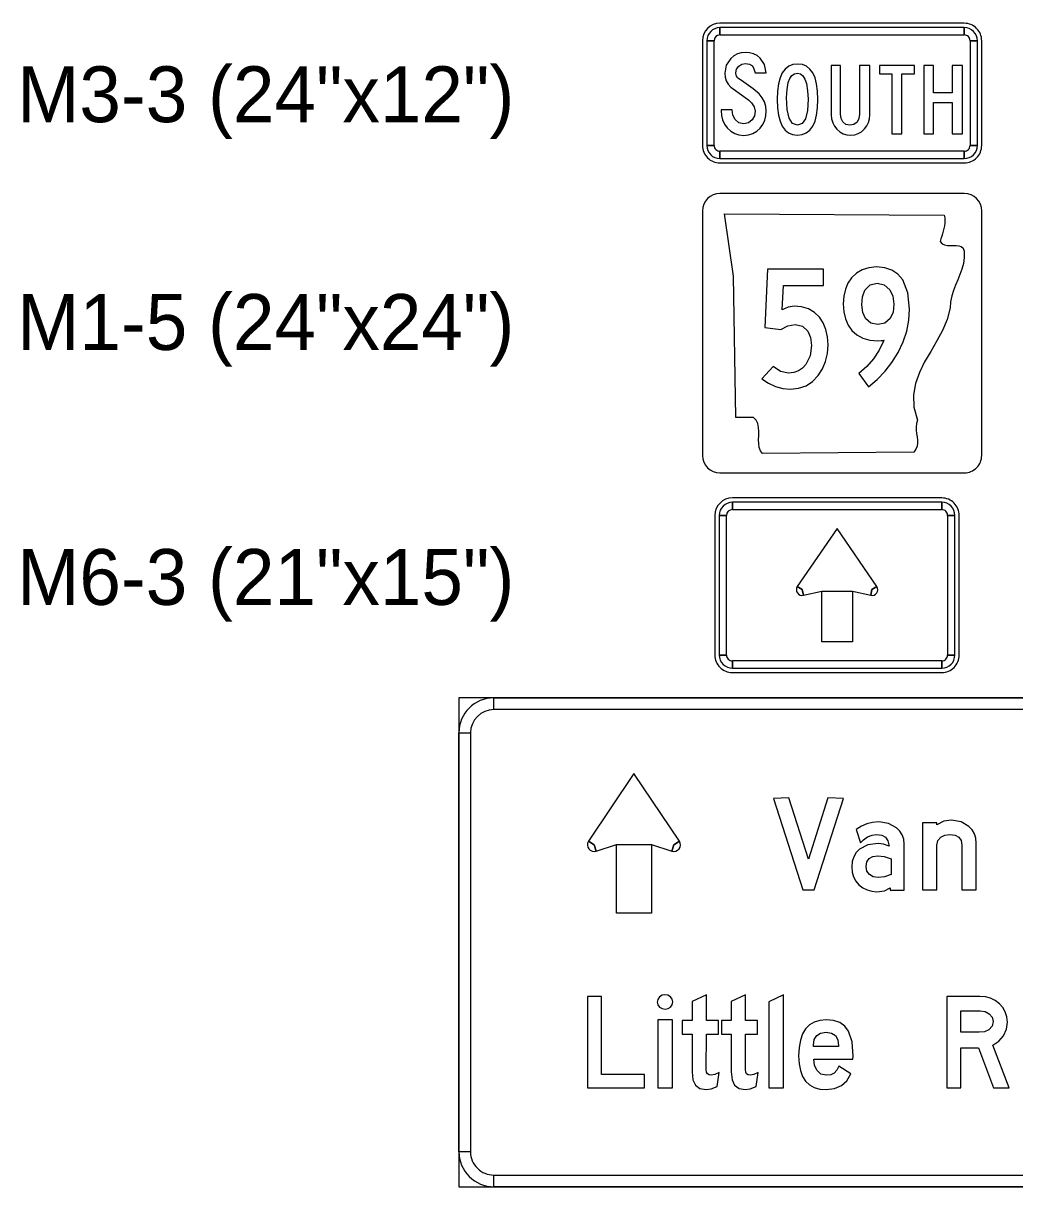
# Model space of a CAD drawing. Extents: x 620864 to 620948.6, y 415499.7 to 415559.1.
# Drawn here: x 620881.4 to 620888.5, y 415507.18 to 415515.51 of the extents above; entities that cross this region are included whole.
import ezdxf

# ---------------------------------------------------------------- set-up
doc = ezdxf.new("R2010")
doc.units = 0
doc.layers.add('G-Border-Paper', color=7, linetype='Continuous')
doc.layers.add('SIGNS', color=7, linetype='Continuous')

msp = doc.modelspace()

# ---------------------------------------------------------------- linework, layer by layer
at = {"layer": 'G-Border-Paper'}
for points in [[(620887.9953, 415514.1388), (620887.9999, 415514.1198), (620888.0016, 415514.1003), (620888.0009, 415514.0812), (620887.9986, 415514.0621), (620887.9946, 415514.043), (620887.9899, 415514.0243), (620887.9842, 415514.0052), (620887.9785, 415513.9869), (620887.9732, 415513.9685), (620887.9682, 415513.9501), (620887.9822, 415513.934), (620887.9996, 415513.9248), (620888.0193, 415513.9208), (620888.0407, 415513.9204), (620888.0621, 415513.9211), (620888.0828, 415513.9215), (620888.1018, 415513.9193), (620888.1185, 415513.9131), (620888.1316, 415513.9009), (620888.1396, 415513.8808), (620888.1403, 415513.8352), (620888.1346, 415513.7926), (620888.1239, 415513.7523), (620888.1095, 415513.7137), (620888.0938, 415513.6755), (620888.0777, 415513.6377), (620888.0627, 415513.5992), (620888.0507, 415513.5595), (620888.0424, 415513.518), (620888.0404, 415513.474), (620888.0183, 415513.3918), (620887.9845, 415513.3136), (620887.9438, 415513.2379), (620887.8996, 415513.163), (620887.8565, 415513.0885), (620887.8188, 415513.0125), (620887.7907, 415512.934), (620887.7763, 415512.8514), (620887.7797, 415512.764), (620887.8054, 415512.6704), (620887.7977, 415512.6472), (620887.7951, 415512.6234), (620887.7957, 415512.5995), (620887.7987, 415512.5753), (620887.8021, 415512.5514), (620887.8048, 415512.5279), (620887.8054, 415512.5048), (620887.8021, 415512.4831), (620887.7937, 415512.4619), (620887.7783, 415512.442), (620886.6946, 415512.4321), (620886.6799, 415512.4519), (620886.6716, 415512.4758), (620886.6679, 415512.5022), (620886.6676, 415512.5305), (620886.6682, 415512.5602), (620886.6686, 415512.5896), (620886.6666, 415512.6186), (620886.6609, 415512.6454), (620886.6499, 415512.6696), (620886.6315, 415512.6902), (620886.5052, 415512.6902), (620886.4871, 415513.702), (620886.4236, 415514.1487), (620887.9953, 415514.1388), (620887.9953, 415514.1388)], [(620886.6902, 415512.9672), (620886.7379, 415512.9342), (620886.7878, 415512.9109), (620886.84, 415512.8971), (620886.8947, 415512.8925), (620886.954, 415512.8985), (620887.0071, 415512.9166), (620887.0541, 415512.9471), (620887.095, 415512.9902), (620887.1257, 415513.0376), (620887.1476, 415513.0902), (620887.1608, 415513.1477), (620887.1654, 415513.2107), (620887.1616, 415513.2681), (620887.1499, 415513.3203), (620887.1307, 415513.3664), (620887.1035, 415513.407), (620887.067, 415513.4415), (620887.0246, 415513.4665), (620886.9756, 415513.4814), (620886.921, 415513.4866), (620886.8797, 415513.4799), (620886.8361, 415513.4598), (620886.8454, 415513.6352), (620887.1324, 415513.6352), (620887.1324, 415513.7507), (620886.7317, 415513.7507), (620886.7112, 415513.3348), (620886.8276, 415513.3198), (620886.8766, 415513.3458), (620886.9295, 415513.3546), (620886.9816, 415513.3427), (620887.0195, 415513.3079), (620887.0391, 415513.2619), (620887.0458, 415513.2049), (620887.0357, 415513.1302), (620887.0058, 415513.0691), (620886.9814, 415513.042), (620886.9526, 415513.0232), (620886.9194, 415513.0115), (620886.882, 415513.008), (620886.8247, 415513.0196), (620886.7709, 415513.0549)]]:
    msp.add_lwpolyline(points, close=True, dxfattribs=at)
for points in [[(620887.3857, 415513.0041), (620887.4546, 415512.909), (620887.517, 415512.9618), (620887.573, 415513.0203), (620887.6225, 415513.0842), (620887.6658, 415513.1539), (620887.7019, 415513.2303), (620887.7282, 415513.3074), (620887.7436, 415513.3853), (620887.7491, 415513.464), (620887.7365, 415513.5829), (620887.6991, 415513.6743), (620887.6642, 415513.7149), (620887.6215, 415513.744), (620887.5704, 415513.7613), (620887.5116, 415513.7673), (620887.4572, 415513.7623), (620887.4094, 415513.7479), (620887.3679, 415513.7237), (620887.3331, 415513.6898), (620887.3071, 415513.6512), (620887.2885, 415513.6073), (620887.2774, 415513.558), (620887.2738, 415513.5037), (620887.2774, 415513.4463), (620887.289, 415513.3955), (620887.3078, 415513.3512), (620887.3349, 415513.3133), (620887.3708, 415513.2803), (620887.4136, 415513.2568), (620887.4634, 415513.2429), (620887.5201, 415513.2383), (620887.5441, 415513.2398), (620887.5675, 415513.2416), (620887.565, 415513.2416), (620887.5315, 415513.1725), (620887.4904, 415513.1101), (620887.4417, 415513.0539), (620887.3857, 415513.0041)], [(620887.6369, 415513.5005), (620887.63, 415513.4438), (620887.6095, 415513.3992), (620887.5717, 415513.3657), (620887.5201, 415513.3546), (620887.4701, 415513.3651), (620887.4332, 415513.3974), (620887.4126, 415513.4412), (620887.4059, 415513.4961), (620887.4115, 415513.5542), (620887.429, 415513.6011), (620887.4652, 415513.639), (620887.516, 415513.6517), (620887.5675, 415513.6399), (620887.607, 415513.6045), (620887.6294, 415513.5573), (620887.6369, 415513.5005)]]:
    msp.add_lwpolyline(points, dxfattribs=at)
at = {"layer": 'SIGNS'}
for p, q in [((620888.1403, 415515.5122), (620886.3903, 415515.5122)), ((620886.3903, 415515.4289), (620886.3903, 415515.481)), ((620888.1403, 415515.481), (620888.1403, 415515.4289)), ((620886.2653, 415515.3872), (620886.2653, 415514.6372)), ((620886.2966, 415515.3872), (620886.3487, 415515.3872)), ((620888.182, 415515.3872), (620888.2341, 415515.3872)), ((620888.2653, 415514.6372), (620888.2653, 415515.3872)), ((620886.3487, 415514.6372), (620886.2966, 415514.6372)), ((620888.2341, 415514.6372), (620888.182, 415514.6372)), ((620886.3903, 415514.5435), (620886.3903, 415514.5956)), ((620888.1403, 415514.5956), (620888.1403, 415514.5435)), ((620886.3903, 415514.5122), (620888.1403, 415514.5122)), ((620888.1403, 415514.2932), (620886.3903, 415514.2932)), ((620886.2653, 415514.1682), (620886.2653, 415512.4182)), ((620888.2653, 415512.4182), (620888.2653, 415514.1682)), ((620886.2653, 415512.4182), (620886.2653, 415512.4182)), ((620886.3903, 415512.2932), (620888.1403, 415512.2932)), ((620887.9793, 415512.1134), (620886.4793, 415512.1134)), ((620886.4793, 415512.0301), (620886.4793, 415512.0821)), ((620887.9793, 415512.0821), (620887.9793, 415512.0301)), ((620886.3543, 415511.9884), (620886.3543, 415510.9884)), ((620886.3855, 415511.9884), (620886.4376, 415511.9884)), ((620888.0209, 415511.9884), (620888.073, 415511.9884)), ((620888.1043, 415510.9884), (620888.1043, 415511.9884)), ((620886.9793, 415511.4571), (620886.944, 415511.4794)), ((620886.9886, 415511.4165), (620886.9793, 415511.4571)), ((620887.4793, 415511.4571), (620887.4699, 415511.4165)), ((620887.5145, 415511.4794), (620887.4793, 415511.4571)), ((620886.4376, 415510.9884), (620886.3855, 415510.9884)), ((620886.4793, 415510.8946), (620886.4793, 415510.9467)), ((620887.9793, 415510.9467), (620887.9793, 415510.8946)), ((620888.073, 415510.9884), (620888.0209, 415510.9884)), ((620886.4793, 415510.8634), (620887.9793, 415510.8634)), ((620892.5209, 415510.6817), (620884.5209, 415510.6817)), ((620884.5209, 415510.6817), (620884.5209, 415507.1817)), ((620884.7709, 415510.5984), (620884.7709, 415510.6817)), ((620884.5209, 415510.4317), (620884.6042, 415510.4317)), ((620885.489, 415509.6309), (620885.4481, 415509.6562)), ((620885.5036, 415509.585), (620885.489, 415509.6309)), ((620886.0594, 415509.6309), (620886.0448, 415509.585)), ((620886.1003, 415509.6562), (620886.0594, 415509.6309)), ((620884.6042, 415507.4317), (620884.5209, 415507.4317)), ((620884.7709, 415507.1817), (620884.7709, 415507.265)), ((620884.5209, 415507.1817), (620892.5209, 415507.1817)), ((620884.5209, 415507.1817), (620884.5209, 415507.1817)), ((620884.5209, 415507.1817), (620884.5209, 415507.1817))]:
    msp.add_line(p, q, dxfattribs=at)
for points in [[(620888.1403, 415515.481), (620886.3903, 415515.481), (620886.3903, 415515.4289), (620888.1403, 415515.4289), (620888.1403, 415515.481), (620888.1403, 415515.481)], [(620886.2966, 415515.3872), (620886.2966, 415514.6372), (620886.3487, 415514.6372), (620886.3487, 415515.3872), (620886.2966, 415515.3872), (620886.2966, 415515.3872)], [(620888.2341, 415514.6372), (620888.2341, 415515.3872), (620888.182, 415515.3872), (620888.182, 415514.6372), (620888.2341, 415514.6372), (620888.2341, 415514.6372)], [(620886.399, 415514.8925), (620886.399, 415514.8872), (620886.4014, 415514.8524), (620886.4097, 415514.8201), (620886.4237, 415514.7905), (620886.4433, 415514.7635), (620886.468, 415514.7397), (620886.4961, 415514.7229), (620886.5269, 415514.7127), (620886.5611, 415514.7094), (620886.5951, 415514.7125), (620886.6261, 415514.7225), (620886.6536, 415514.7388), (620886.6782, 415514.7619), (620886.6973, 415514.7884), (620886.711, 415514.8176), (620886.7192, 415514.8494), (620886.722, 415514.8841), (620886.7186, 415514.9172), (620886.709, 415514.9487), (620886.6929, 415514.9786), (620886.6707, 415515.0068), (620886.6275, 415515.0439), (620886.5611, 415515.0895), (620886.5171, 415515.1225), (620886.5077, 415515.1391), (620886.5045, 415515.1582), (620886.5096, 415515.1838), (620886.525, 415515.2054), (620886.5473, 415515.2199), (620886.5737, 415515.2248), (620886.6021, 415515.2201), (620886.6228, 415515.2064), (620886.634, 415515.187), (620886.6425, 415515.1584), (620886.722, 415515.1584), (620886.709, 415515.2168), (620886.6787, 415515.2627), (620886.6565, 415515.2806), (620886.6314, 415515.2935), (620886.6028, 415515.3013), (620886.5715, 415515.3039), (620886.5423, 415515.3011), (620886.5155, 415515.2928), (620886.4906, 415515.279), (620886.4682, 415515.2597), (620886.4356, 415515.2117), (620886.4249, 415515.1559), (620886.4276, 415515.1272), (620886.4357, 415515.1009), (620886.4494, 415515.0765), (620886.4687, 415515.0545), (620886.5616, 415514.988), (620886.5962, 415514.9618), (620886.6175, 415514.9422), (620886.6365, 415514.9137), (620886.643, 415514.8832), (620886.6373, 415514.8494), (620886.621, 415514.8206), (620886.594, 415514.7996), (620886.5611, 415514.7926), (620886.5259, 415514.8003), (620886.4987, 415514.8238), (620886.4827, 415514.855), (620886.478, 415514.8925)], [(620887.1877, 415515.2109), (620887.1877, 415514.8559), (620887.1905, 415514.8271), (620887.1983, 415514.8005), (620887.2109, 415514.776), (620887.2287, 415514.7536), (620887.2497, 415514.7348), (620887.2734, 415514.7216), (620887.2995, 415514.7136), (620887.3281, 415514.711), (620887.3558, 415514.7137), (620887.3814, 415514.722), (620887.4047, 415514.736), (620887.4259, 415514.7557), (620887.4427, 415514.7783), (620887.4548, 415514.8027), (620887.462, 415514.829), (620887.4645, 415514.8574), (620887.4645, 415515.2109), (620887.3896, 415515.2109), (620887.3896, 415514.8603), (620887.3852, 415514.8295), (620887.3724, 415514.8053), (620887.35, 415514.7877), (620887.3207, 415514.7819), (620887.2929, 415514.7878), (620887.2716, 415514.8063), (620887.259, 415514.8308), (620887.2549, 415514.8603), (620887.2549, 415515.2109)], [(620887.6217, 415514.7206), (620887.6929, 415514.7206), (620887.6929, 415515.1494), (620887.7844, 415515.1494), (620887.7844, 415515.2109), (620887.5322, 415515.2109), (620887.5322, 415515.1494), (620887.6217, 415515.1494)], [(620887.8517, 415514.7206), (620887.9189, 415514.7206), (620887.9189, 415514.9456), (620888.0536, 415514.9456), (620888.0536, 415514.7206), (620888.1285, 415514.7206), (620888.1285, 415515.2109), (620888.0536, 415515.2109), (620888.0536, 415515.0143), (620887.9189, 415515.0143), (620887.9189, 415515.2109), (620887.8517, 415515.2109)], [(620886.3903, 415514.5435), (620888.1403, 415514.5435), (620888.1403, 415514.5956), (620886.3903, 415514.5956), (620886.3903, 415514.5435), (620886.3903, 415514.5435)], [(620887.9793, 415512.0821), (620886.4793, 415512.0821), (620886.4793, 415512.0301), (620887.9793, 415512.0301), (620887.9793, 415512.0821), (620887.9793, 415512.0821)], [(620886.3855, 415511.9884), (620886.3855, 415510.9884), (620886.4376, 415510.9884), (620886.4376, 415511.9884), (620886.3855, 415511.9884), (620886.3855, 415511.9884)], [(620888.073, 415510.9884), (620888.073, 415511.9884), (620888.0209, 415511.9884), (620888.0209, 415510.9884), (620888.073, 415510.9884), (620888.073, 415510.9884)], [(620887.2293, 415511.8946), (620886.944, 415511.4794), (620886.9793, 415511.4571), (620886.9886, 415511.4165), (620887.1199, 415511.4467), (620887.3386, 415511.4467), (620887.4699, 415511.4165), (620887.4793, 415511.4571), (620887.5145, 415511.4794), (620887.2293, 415511.8946), (620887.2293, 415511.8946)], [(620887.3386, 415511.0821), (620887.1199, 415511.0821), (620887.1199, 415511.4467), (620887.3386, 415511.4467), (620887.3386, 415511.0821), (620887.3386, 415511.0821)], [(620886.4793, 415510.8946), (620887.9793, 415510.8946), (620887.9793, 415510.9467), (620886.4793, 415510.9467), (620886.4793, 415510.8946), (620886.4793, 415510.8946)], [(620892.2709, 415510.5984), (620884.7709, 415510.5984), (620884.7709, 415510.6817), (620892.2709, 415510.6817), (620892.2709, 415510.5984), (620892.2709, 415510.5984)], [(620884.6042, 415510.4317), (620884.6042, 415507.4317), (620884.5209, 415507.4317), (620884.5209, 415510.4317), (620884.6042, 415510.4317), (620884.6042, 415510.4317)], [(620885.7742, 415510.14), (620885.4481, 415509.6562), (620885.489, 415509.6309), (620885.5036, 415509.585), (620885.6492, 415509.6314), (620885.8992, 415509.6314), (620886.0448, 415509.585), (620886.0594, 415509.6309), (620886.1003, 415509.6562), (620885.7742, 415510.14), (620885.7742, 415510.14)], [(620886.7742, 415509.9605), (620886.9831, 415509.3067), (620887.0642, 415509.3067), (620887.2752, 415509.9605), (620887.1638, 415509.9659), (620887.0248, 415509.5262), (620886.8829, 415509.9659)], [(620887.8409, 415509.3067), (620887.9434, 415509.3067), (620887.9434, 415509.627), (620887.9506, 415509.6598), (620887.9729, 415509.685), (620888.0013, 415509.6989), (620888.0367, 415509.7035), (620888.0742, 415509.6985), (620888.1013, 415509.6841), (620888.1175, 415509.6601), (620888.1228, 415509.6264), (620888.1228, 415509.3067), (620888.2264, 415509.3067), (620888.2264, 415509.642), (620888.223, 415509.6768), (620888.2133, 415509.7085), (620888.1966, 415509.7367), (620888.1738, 415509.762), (620888.1172, 415509.7955), (620888.0498, 415509.8067), (620887.9941, 415509.7981), (620887.9436, 415509.7722), (620887.9436, 415509.7881), (620887.8409, 415509.7881)], [(620885.8992, 415509.14), (620885.6492, 415509.14), (620885.6492, 415509.6314), (620885.8992, 415509.6314), (620885.8992, 415509.14), (620885.8992, 415509.14)], [(620885.4409, 415507.89), (620885.8497, 415507.89), (620885.8497, 415507.9856), (620885.5424, 415507.9856), (620885.5424, 415508.5439), (620885.4409, 415508.5439)], [(620885.9963, 415508.5567), (620885.9761, 415508.5525), (620885.9579, 415508.5404), (620885.945, 415508.5232), (620885.9409, 415508.5042), (620885.945, 415508.4845), (620885.9579, 415508.4685), (620885.9765, 415508.4578), (620885.9982, 415508.4541), (620886.0196, 415508.4575), (620886.0374, 415508.4682), (620886.0494, 415508.4841), (620886.0536, 415508.5048), (620886.0494, 415508.5244), (620886.0368, 415508.5412), (620886.0182, 415508.5526)], [(620886.1209, 415508.2746), (620886.1908, 415508.2746), (620886.1908, 415508.0038), (620886.197, 415507.9483), (620886.2158, 415507.9088), (620886.247, 415507.8851), (620886.2909, 415507.8773), (620886.3268, 415507.8826), (620886.3709, 415507.8988), (620886.3846, 415507.9994), (620886.3528, 415507.9845), (620886.3285, 415507.9797), (620886.3128, 415507.9822), (620886.3017, 415507.9897), (620886.2951, 415508.0022), (620886.2929, 415508.02), (620886.2935, 415508.2746), (620886.3792, 415508.2746), (620886.3792, 415508.3714), (620886.2935, 415508.3714), (620886.2935, 415508.5567), (620886.1908, 415508.5072), (620886.1908, 415508.3714), (620886.1209, 415508.3714)], [(620886.4009, 415508.2746), (620886.4708, 415508.2746), (620886.4708, 415508.0038), (620886.477, 415507.9483), (620886.4958, 415507.9088), (620886.527, 415507.8851), (620886.5709, 415507.8773), (620886.6068, 415507.8826), (620886.6509, 415507.8988), (620886.6646, 415507.9994), (620886.6328, 415507.9845), (620886.6085, 415507.9797), (620886.5928, 415507.9822), (620886.5817, 415507.9897), (620886.5751, 415508.0022), (620886.5729, 415508.02), (620886.5735, 415508.2746), (620886.6592, 415508.2746), (620886.6592, 415508.3714), (620886.5735, 415508.3714), (620886.5735, 415508.5567), (620886.4708, 415508.5072), (620886.4708, 415508.3714), (620886.4009, 415508.3714)], [(620886.7409, 415507.89), (620886.8464, 415507.89), (620886.8464, 415508.5567), (620886.7409, 415508.5062)], [(620885.9454, 415507.89), (620886.051, 415507.89), (620886.051, 415508.3772), (620885.9454, 415508.3772)], [(620884.7709, 415507.265), (620892.2709, 415507.265), (620892.2709, 415507.1817), (620884.7709, 415507.1817), (620884.7709, 415507.265), (620884.7709, 415507.265)]]:
    msp.add_lwpolyline(points, close=True, dxfattribs=at)
for points in [[(620887.0922, 415514.9665), (620887.0898, 415515.0258), (620887.0831, 415515.0775), (620887.0718, 415515.1211), (620887.0561, 415515.157), (620887.0354, 415515.1846), (620887.0106, 415515.2046), (620886.9812, 415515.2165), (620886.9474, 415515.2206), (620886.9129, 415515.2165), (620886.883, 415515.2046), (620886.8577, 415515.1846), (620886.8371, 415515.157), (620886.8211, 415515.1211), (620886.8097, 415515.0775), (620886.8027, 415515.0258), (620886.8005, 415514.9665), (620886.8026, 415514.9064), (620886.8093, 415514.8546), (620886.8206, 415514.8105), (620886.8364, 415514.7748), (620886.8565, 415514.7467), (620886.8813, 415514.7269), (620886.9106, 415514.7149), (620886.9444, 415514.711), (620886.979, 415514.7149), (620887.009, 415514.7269), (620887.0344, 415514.7467), (620887.0553, 415514.7748), (620887.0714, 415514.8105), (620887.0829, 415514.8546), (620887.0898, 415514.9064), (620887.0922, 415514.9665)], [(620887.0216, 415514.9687), (620887.0168, 415514.887), (620887.0024, 415514.8289), (620886.9785, 415514.7939), (620886.9451, 415514.7823), (620886.9112, 415514.7946), (620886.887, 415514.8319), (620886.8726, 415514.8939), (620886.8678, 415514.9811), (620886.8708, 415515.0389), (620886.8801, 415515.087), (620886.8912, 415515.1165), (620886.9058, 415515.1378), (620886.9237, 415515.1504), (620886.9451, 415515.1547), (620886.9662, 415515.1501), (620886.9841, 415515.1361), (620886.9986, 415515.1129), (620887.0099, 415515.0805), (620887.0186, 415515.0296), (620887.0216, 415514.9687)], [(620886.3903, 415514.2932), (620886.3903, 415514.2932)], [(620888.1403, 415514.2932), (620888.1403, 415514.2932)], [(620886.2653, 415514.1682), (620886.2653, 415514.1682)], [(620886.3903, 415512.2932), (620886.3903, 415512.2932)], [(620888.1403, 415512.2932), (620888.1403, 415512.2932)], [(620887.6084, 415509.3061), (620887.7099, 415509.3061), (620887.7099, 415509.635), (620887.7064, 415509.6697), (620887.6959, 415509.7007), (620887.6785, 415509.7282), (620887.6545, 415509.7522), (620887.5972, 415509.7834), (620887.5279, 415509.7939), (620887.484, 415509.7904), (620887.4425, 415509.7804), (620887.4033, 415509.7638), (620887.3664, 415509.7405), (620887.3967, 415509.643), (620887.4181, 415509.6667), (620887.4473, 415509.6863), (620887.4798, 415509.6995), (620887.5114, 415509.7041), (620887.5497, 415509.6989), (620887.5767, 415509.6837), (620887.5922, 415509.658), (620887.6018, 415509.6198), (620887.5619, 415509.6348), (620887.5241, 415509.64), (620887.4502, 415509.6296), (620887.3908, 415509.5985), (620887.3658, 415509.5737), (620887.3482, 415509.5444), (620887.3375, 415509.5106), (620887.3342, 415509.4723), (620887.3374, 415509.4349), (620887.347, 415509.401), (620887.363, 415509.3706), (620887.3859, 415509.3439), (620887.4131, 415509.3219), (620887.4437, 415509.3064), (620887.4772, 415509.2969), (620887.514, 415509.2939), (620887.5686, 415509.3009), (620887.6084, 415509.3225), (620887.6084, 415509.3061)], [(620887.6162, 415509.4176), (620887.5691, 415509.4016), (620887.5232, 415509.3964), (620887.4884, 415509.4012), (620887.4607, 415509.4162), (620887.4428, 415509.4405), (620887.4367, 415509.4737), (620887.4419, 415509.507), (620887.458, 415509.531), (620887.4844, 415509.5455), (620887.5219, 415509.5503), (620887.5674, 415509.5451), (620887.6162, 415509.5296), (620887.6162, 415509.4176)], [(620888.0142, 415507.89), (620888.1167, 415507.89), (620888.1167, 415508.1768), (620888.2419, 415508.1768), (620888.3485, 415507.89), (620888.4624, 415507.89), (620888.3459, 415508.1951), (620888.3877, 415508.2234), (620888.4206, 415508.263), (620888.4416, 415508.3095), (620888.4487, 415508.3595), (620888.445, 415508.398), (620888.4342, 415508.4331), (620888.4164, 415508.4643), (620888.3916, 415508.4922), (620888.3615, 415508.5146), (620888.3282, 415508.5308), (620888.2918, 415508.5404), (620888.2522, 415508.5439), (620888.0142, 415508.5433), (620888.0142, 415507.89)], [(620888.1167, 415508.2874), (620888.1167, 415508.4413), (620888.2531, 415508.4413), (620888.2892, 415508.4361), (620888.3196, 415508.4205), (620888.3405, 415508.3958), (620888.3475, 415508.364), (620888.3397, 415508.3303), (620888.3166, 415508.3051), (620888.2854, 415508.2911), (620888.2478, 415508.2874), (620888.1167, 415508.2874)], [(620887.2416, 415508.0443), (620887.2286, 415508.0158), (620887.2094, 415507.9958), (620887.1837, 415507.9838), (620887.1521, 415507.9797), (620887.1138, 415507.9888), (620887.0847, 415508.016), (620887.0685, 415508.0513), (620887.0624, 415508.0951), (620887.3432, 415508.0951), (620887.3438, 415508.1172), (620887.337, 415508.2201), (620887.3115, 415508.2959), (620887.2843, 415508.3313), (620887.2488, 415508.3568), (620887.2045, 415508.372), (620887.1519, 415508.3772), (620887.1054, 415508.373), (620887.0651, 415508.361), (620887.0311, 415508.3406), (620887.0034, 415508.3125), (620886.9818, 415508.276), (620886.9664, 415508.2315), (620886.9571, 415508.1791), (620886.9542, 415508.1186), (620886.9571, 415508.0619), (620886.9664, 415508.0128), (620886.9818, 415507.9713), (620887.0037, 415507.9375), (620887.0313, 415507.9109), (620887.0654, 415507.8922), (620887.1056, 415507.8808), (620887.1521, 415507.8773), (620887.2116, 415507.8843), (620887.2607, 415507.9054), (620887.2989, 415507.9407), (620887.3268, 415507.9904), (620887.2416, 415508.0443)], [(620887.239, 415508.1849), (620887.0603, 415508.1849), (620887.0603, 415508.1963), (620887.0659, 415508.236), (620887.0832, 415508.2646), (620887.1116, 415508.2816), (620887.1519, 415508.2874), (620887.1904, 415508.2814), (620887.2178, 415508.2634), (620887.2342, 415508.2334), (620887.2396, 415508.1915), (620887.239, 415508.1849)]]:
    msp.add_lwpolyline(points, dxfattribs=at)
for centre, radius, start, end in [((620886.3903, 415515.3872), 0.125, 90.00021, 179.99985), ((620886.3903, 415515.3872), 0.0937, 90.00021, 179.99985), ((620888.1403, 415515.3872), 0.125, 360, 90.00021), ((620888.1403, 415515.3872), 0.0937, 360, 90.00021), ((620886.3903, 415515.3872), 0.0417, 90.00021, 179.99985), ((620888.1403, 415515.3872), 0.0417, 360, 90.00021), ((620886.3903, 415514.6372), 0.125, 179.99985, 270.00006), ((620886.3903, 415514.6372), 0.0937, 179.99985, 270.00006), ((620886.3903, 415514.6372), 0.0417, 179.99985, 270.00006), ((620888.1403, 415514.6372), 0.125, 270.00006, 0.00027), ((620888.1403, 415514.6372), 0.0937, 270.00006, 0.00027), ((620888.1403, 415514.6372), 0.0417, 270.00006, 0.00027), ((620886.3903, 415514.1682), 0.125, 90.00021, 179.99985), ((620888.1403, 415514.1682), 0.125, 360, 90), ((620886.3903, 415512.4182), 0.125, 180, 270), ((620888.1403, 415512.4182), 0.125, 270.00006, 0.00027), ((620886.4793, 415511.9884), 0.125, 90.00021, 179.99985), ((620887.9793, 415511.9884), 0.125, 360, 90.00021), ((620886.4793, 415511.9884), 0.0937, 90.00021, 179.99985), ((620886.4793, 415511.9884), 0.0417, 90.00021, 179.99985), ((620887.9793, 415511.9884), 0.0937, 360, 90.00021), ((620887.9793, 415511.9884), 0.0417, 360, 90.00021), ((620886.9793, 415511.4571), 0.0417, 147.72456, 282.95062), ((620887.4793, 415511.4571), 0.0417, 257.04949, 32.27555), ((620886.4793, 415510.9884), 0.125, 179.99985, 270.00006), ((620886.4793, 415510.9884), 0.0937, 179.99985, 270.00006), ((620886.4793, 415510.9884), 0.0417, 179.99985, 270.00006), ((620887.9793, 415510.9884), 0.0937, 270.00006, 0.00027), ((620887.9793, 415510.9884), 0.0417, 270.00006, 0.00027), ((620887.9793, 415510.9884), 0.125, 270.00006, 0.00027), ((620884.7709, 415510.4317), 0.25, 90.00021, 179.99985), ((620884.7709, 415510.4317), 0.1667, 90.00021, 179.99985), ((620885.489, 415509.6309), 0.0481, 148.25856, 287.68383), ((620886.0594, 415509.6309), 0.0481, 252.31629, 31.74156), ((620884.7709, 415507.4317), 0.25, 179.99985, 270.00006), ((620884.7709, 415507.4317), 0.1667, 179.99985, 270.00006)]:
    msp.add_arc(centre, radius, start, end, dxfattribs=at)

# ---------------------------------------------------------------- texts
for s, p in [('M3-3 (24"x12")', (620881.3572, 415514.804)), ('M1-5 (24"x24")', (620881.3572, 415513.1732)), ('M6-3 (21"x15")', (620881.3572, 415511.3476))]:
    msp.add_text(s, height=0.4, rotation=0, dxfattribs=at).set_placement(p)

doc.saveas('drawing.dxf')
